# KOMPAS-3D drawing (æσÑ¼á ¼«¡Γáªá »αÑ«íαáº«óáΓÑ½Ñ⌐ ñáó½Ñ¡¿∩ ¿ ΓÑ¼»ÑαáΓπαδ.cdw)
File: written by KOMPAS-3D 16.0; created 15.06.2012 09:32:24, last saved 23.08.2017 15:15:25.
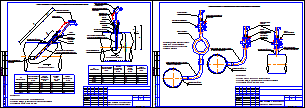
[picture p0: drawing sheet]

Sheets 1-2: A3, landscape

Title block, sheet 1: name: г. Москва, ул. Нежинская, д. 14, к.8 (кв. 1 и кв. 2); sheet number: 1; sheets: 20; sheet format: A3; stored path: W:\Users\smirnov_v\Desktop\Москва\ул. Нежинская, д.14, к.6\Нежинская, д.14, к.6.cdw
Title block, sheet 2: sheet number: 2; sheet number: 20

Views: Вид 2, Вид 3, Вид 4, Вид 5
Referenced files in C:\Program Files (x86)\ASCON\KOMPAS-3D V16\Sys\: spds.lcs, EngSys.lcs, GRAPHIC.LHS
Referenced files: graphic.tdp
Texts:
  МО, Клинский район, д. Решетниково, ул. Центральная, д.14
  GOST Common
  Normal
  List Paragraph
  heading 3
  для схемы
  txt
  краны
  Фоновая заливка
  Т0-элементы
  Размеры, параметризация
  сит. план
  Примечания:
  1. Сварка ручная дуговая по ГОСТ 5264-85.
  2. Сварные швы по ГОСТ 16037-80, вакуумно-плотные.
  3. Электроды МР-3М d=0,4 мм ЛЭЗ.
  Схема монтажа и пломбирования термопреобразователя ТС-Б
  Схема монтажа и пломбирования выносного датчика давления
  Прокладка
  паронитовая
  Пломба ресурсоснабжающей
  организации
  ГОСТ 16037-80-У7- К
  Направление потока
  Термопреобразователь
  сопротивления
  Гильза
  защитная
  Бобышка
  прямая
  Перед установкой термодатчика
  в гильзу залить техническое масло
  трубопровода
  Ду125
  Ду150
  Ду100
  Ду80
  Ду65
  Ду50
  Преобразователь
  температуры,
  L, мм
  Глубина
  погружения
  (0,3-0,7 Ду)
  А, мм
  под ДТ
  B, мм
  Стенка
  S, мм
  Отверстия для
  пломбирования
  элемента
  Пломба d10 мм
  косая
  давления
  Отвод гнутый Ду15 (G 1/2) с резьбой
  из труб по ГОСТ 3262-75
  Кран шаровой трехходовой
  Трубка петлевая
  При температуре теплоносителя
  выше 120 С для монтажа ПД
  на трубопроводе использовать
  петлевую трубку.
  Пломба
  ресурсоснабжающей
  Резьба Ду15 L=50мм
  Кран шаровой
  трехходовой
  подача ГВС
  обратка ГВС
  хвс
  обратка
  POLYLINE_STYLE_0.25_RGB_0_0_0
  стены
  Основная (не является границей для штриховки)
  POLYLINE_STYLE_0.18_RGB_0_0_0
  ХВС
  зеленая
  Красная тонкая
  арматура
  Подача
  Скрытая линия
  Ось Z
  Ось Y
  Ось X
  Образующая трубопровода (проектируемого)
  Трубопровод толщиной 0.6мм (одна линия)
  Трубопровод толщиной 1.2мм (одна линия)
  Трубопровод толщиной 1.0мм (одна линия)
  Трубопровод толщиной 0.8мм (одна линия)
  Трубопровод существующий (одна линия)
  Трубопровод невидимый (одна линия)
  Трубопровод демонтируемый (одна линия)
  Осевая трубопровода
  Осевая трубопровода (демонтируемого)
  Образующая трубопровода (существующего)
  Образующая трубопровода (невидимого)
  Изолированный трубопровод проектируемый (одна линия)
  Изолированный трубопровод существующий (одна линия)
  Образующая изоляции
  Изоляция
  Изолированный трубопровод невидимый (одна линия)
  Штрих пвс 075
  штрих пвс 2,5
  существующее оборудование
  Существующее оборудование
  K5LT_BASIC_RGB_0_0_255_THICK_0.53
  POLYLINE_STYLE_1.51_RGB_0_0_255
  POLYLINE_STYLE_0.50_RGB_128_128_128
  K5LT_AXLED_RGB_255_128_0_SC_1_THICK_0.18
  ACAD_ISO04W100_RGB_0_0_0_SC_1_THICK_0.18
  тонкая черная
  пломбировка
  Провода
  синий штрих
  Стили документа
  кривая построения катета
  G2co
  расход вторичной воды объемный
  расход вторичной воды объемный при 70гр
  Gco
  расход теплоносителя массовый
  расход теплоносит объемн подающ
  расход теплоносит объемн обр
  Лапир
  Ghvs
  Im1
  Im2
  Im3
  Im4
  Im5
  Khvs
  норматив ХВС
  число подъездов
  число этажей
  Nkv
  число квартир
  тепловая нагрузка на отопление
  сумма Q
  Qgvs
  тепловая нагрузка ГВС
  тепловая нагрузка на циркуляцию ГВС
  иммитовставка или под манометр
  ro1
  ro2
  ro3
  ro4
  верх предел темп граф
  нижн предел темп граф
  темп подачи ГВС
  темп обр ГВС
  темр хол воды
  vzdh
  Kchn
  Ktp
  Knp
  beta
  tnv
  Vклап
  KLP
  RPD
  RDS
  PUMP
  ro5
  Переход К-76 x 3-38 x 2-09Г2С ГОСТ 17378-2001
  Переход ГОСТ 17378-2001
  Переход
  ГОСТ
  Сталь 09Г2С ГОСТ 19281-89
  Переход К-76 x 3-45 x 2,5-09Г2С ГОСТ 17378-2001
  Переход К-57 x 3-38 x 2-09Г2С ГОСТ 17378-2001
  Переход К-57 x 3-32 x 2-09Г2С ГОСТ 17378-2001
  Втулка 20x50
  Переход К-108 x 4-57 x 3-09Г2С ГОСТ 17378-2001
  Переход К-45 x 2,5-32 x 2-09Г2С ГОСТ 17378-2001
  Переход К-89 x 3,5-45 x 2,5-09Г2С ГОСТ 17378-2001
  Переход К-133 x 5-108 x 4-09Г2С ГОСТ 17378-2001
  Переход К-159 x 4,5-89 x 3,5-09Г2С ГОСТ 17378-2001
  Переход К-45 x 2,5-38 x 2-09Г2С ГОСТ 17378-2001
  Фланец 1-32-1 Ст3сп ГОСТ 12820-80
  Фланцы
  Фланец
  квадратный
  Ст3сп
  Ст3сп ГОСТ 380-2005
  Переход К-57 x 3-45 x 2,5-09Г2С ГОСТ 17378-2001
  Переход К-76 x 3-57 x 3-09Г2С ГОСТ 17378-2001
  Фланец 1-50-16 Ст3сп ГОСТ 12821-80
  Переход К-89 x 3,5-76 x 3,5-09Г2С ГОСТ 17378-2001
  Переход К-108 x 4-89 x 3,5-09Г2С ГОСТ 17378-2001
  Тройник 159 x 4,5-09Г2С ГОСТ 17376-2001
  Тройники ГОСТ 17376-2001
  Тройник
  Отвод 90-159 x 4-09Г2С ГОСТ 17375-2001
  Отвод ГОСТ 17375-2001
  Отвод
  Переход К-108 x 4-76 x 3,5-09Г2С ГОСТ 17378-2001
  Переход К-159 x 4,5-108 x 4-09Г2С ГОСТ 17378-2001
  Переход К-133 x 5-76 x 3,5-09Г2С ГОСТ 17378-2001
  Переход К-133 x 4-89 x 3,5-09Г2С ГОСТ 17378-2001
  Переход К-1-42,4 x 2,6-21,3 x 2-TS10 ГОСТ 17378-2001
  TS10
  Сталь TS10 ИСО 2604/2-75
  Фланец 1-20-16 Ст3сп ГОСТ 12820-80
  Лит-Масса-Масштаб
  Материал-Предприятие
  Title Specification
  Body Specification ( left align )
  Body Specificaton ( centered )
  Поз.
  Кол.
  Приме-
  чание
  Таблица спецификации
  Засыпка
  Штрих3
  Штрих2
  Штрих1
  Песок
  Штр0.5пр7
  Штр0.5пр12
  Штр0.3пр10
  Штр1.4пр21.21
  Штр1пр15
  Штр2.12пр35
  Штр1.5пр25
  Штр2.82пр42.42
  Штр2пр30
  SACNCR_ISO 1
  Электрощитовая
  Пр-1
  Ок-1
  вапвыапвы
  Обозначение стандарта
  Типоразмер
  Схема монтажа и пломбирования
  термопреобразователя ТС-Б
  Разраб.
  Пров.
  Т.контр.
  Н.контр.
  Утв.
  Рабочие чертежи основного комплекта. ГОСТ Р 21.1101-2009 Ф3
  Стадия
  Лист
  Листов
  Изм.
  Кол.уч.
  №док.
  Подп.
  Дата
  Изменение
  Номер документа
  Подпись
  Наименование объекта строительства, в состав которого входит здание, наим. микр
  Наименование здания (сооружения)
  Порядковый номер листа
  Количество листов в документе
  Наименование изображения
  Индекс предприятия, выпускающего документ
  Инв. № подл.
  Подп. и дата
  Взам. инв. №
  Инвентарный номер подлинника
  Подпись принявшего подлинник на хранение
  Инвентарный номер подлинника, взамен которого выпущен данный подлинник
  Согласовано
  Формат листа
  Согласование
  03 Рабочие чертежи основного комплекта. ГОСТ Р 21.1101-2009 Ф3
  выносного датчика давления
Dimensions and other numbers on the sheet: 0; 120; 76; 40; 4,0; 100; 56; 80; 36,5; 3,5; 60; 24,5; 32; 1/2 чувствительного; 45; 60 (80); 50; 351; 1; 09Г2С; 2; 3; 4; 6; 8; 12; 16; 17; 19; 20; 21; 22; 23; 24; 25; 26; 30; 31; 33; 34; 52; 64; 65; 66; 67; 69; 70; 71; 72; 73; 74; 75; 5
